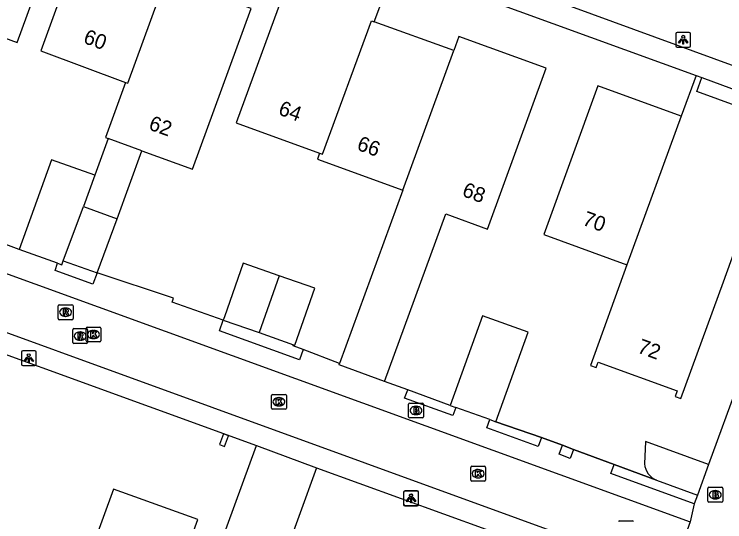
# Model space of a CAD drawing. Extents: x 155275 to 156263, y 382654 to 383635.
# Drawn here: x 156037.12 to 156084.89, y 383048.16 to 383082.31 of the extents above; entities that cross this region are included whole.
import ezdxf

# ---------------------------------------------------------------- set-up
doc = ezdxf.new("R2010")
doc.units = 0
for name, color, linetype in [('IMGEO_Brandkraan', 7, 'Continuous'), ('IMGEO_Haag', 7, 'Continuous'), ('IMGEO_Hek', 7, 'Continuous'), ('IMGEO_Kolk', 7, 'Continuous'), ('IMGEO_Lichtpunt', 7, 'Continuous'), ('IMGEO_Pand', 7, 'Continuous'), ('IMGEO_Pand_nummerreeks', 7, 'Continuous'), ('IMGEO_Rijbaan_lokaal_open', 7, 'Continuous'), ('IMGEO_Rioolput', 7, 'Continuous'), ('IMGEO_Voetpad_open', 7, 'Continuous')]:
    doc.layers.add(name, color=color, linetype=linetype)

msp = doc.modelspace()

# ---------------------------------------------------------------- linework, layer by layer
at = {"layer": 'IMGEO_Brandkraan'}
for p, q in [((156063.632, 383055.222), (156063.632, 383056.074)), ((156063.707, 383056.148), (156064.559, 383056.148)), ((156064.633, 383056.074), (156064.633, 383055.222)), ((156064.12, 383055.928), (156064.145, 383055.928)), ((156064.559, 383055.148), (156063.707, 383055.148)), ((156064.143, 383055.368), (156064.118, 383055.368)), ((156083.749, 383049.552), (156083.749, 383050.404)), ((156083.824, 383050.478), (156084.676, 383050.478)), ((156084.75, 383050.404), (156084.75, 383049.552)), ((156084.237, 383050.258), (156084.262, 383050.258)), ((156084.676, 383049.478), (156083.824, 383049.478)), ((156084.26, 383049.698), (156084.235, 383049.698))]:
    msp.add_line(p, q, dxfattribs=at)
for points in [[(156063.632, 383055.222), (156063.632, 383056.074)], [(156063.707, 383056.148), (156064.559, 383056.148)], [(156064.633, 383056.074), (156064.633, 383055.222)], [(156063.98, 383055.848), (156063.98, 383055.448), (156064.193, 383055.448)], [(156064.211, 383055.848), (156063.98, 383055.848)], [(156064.159, 383055.767), (156064.105, 383055.767), (156064.105, 383055.691)], [(156064.105, 383055.691), (156064.158, 383055.691)], [(156064.167, 383055.615), (156064.105, 383055.615), (156064.105, 383055.534)], [(156064.559, 383055.148), (156063.707, 383055.148)], [(156064.105, 383055.534), (156064.167, 383055.534)], [(156083.749, 383049.552), (156083.749, 383050.404)], [(156083.824, 383050.478), (156084.676, 383050.478)], [(156084.75, 383050.404), (156084.75, 383049.552)], [(156084.097, 383050.178), (156084.097, 383049.778), (156084.31, 383049.778)], [(156084.328, 383050.178), (156084.097, 383050.178)], [(156084.276, 383050.097), (156084.222, 383050.097), (156084.222, 383050.021)], [(156084.222, 383050.021), (156084.275, 383050.021)], [(156084.284, 383049.945), (156084.222, 383049.945), (156084.222, 383049.864)], [(156084.222, 383049.864), (156084.284, 383049.864)], [(156084.676, 383049.478), (156083.824, 383049.478)]]:
    msp.add_lwpolyline(points, dxfattribs=at)
for centre, radius, start, end in [((156063.709, 383056.072), 0.0765, 91.552, 178.448), ((156063.709, 383056.072), 0.0765, 91.552, 178.448), ((156064.557, 383056.072), 0.0765, 1.552, 88.448), ((156064.557, 383056.072), 0.0765, 1.552, 88.448), ((156064.16, 383055.729), 0.0379, 267.8285, 90.9355), ((156064.168, 383055.574), 0.0404, 269.8759, 90.5077), ((156064.215, 383055.703), 0.145, 59.4692, 91.5367), ((156064.24, 383055.75), 0.0922, 285.5137, 58.1501), ((156064.245, 383055.558), 0.105, 301.3115, 78.989), ((156063.709, 383055.224), 0.0765, 181.552, 268.448), ((156063.709, 383055.224), 0.0765, 181.552, 268.448), ((156064.199, 383055.699), 0.251, 268.6676, 293.5347), ((156064.557, 383055.224), 0.0765, 271.552, 358.448), ((156064.557, 383055.224), 0.0765, 271.552, 358.448), ((156083.826, 383050.402), 0.0765, 91.552, 178.448), ((156083.826, 383050.402), 0.0765, 91.552, 178.448), ((156084.674, 383050.402), 0.0765, 1.552, 88.448), ((156084.674, 383050.402), 0.0765, 1.552, 88.448), ((156084.277, 383050.059), 0.0379, 267.8285, 90.9355), ((156084.285, 383049.904), 0.0404, 269.8759, 90.5077), ((156084.332, 383050.033), 0.145, 59.4692, 91.5367), ((156084.357, 383050.08), 0.0922, 285.5137, 58.1501), ((156084.362, 383049.888), 0.105, 301.3115, 78.989), ((156083.826, 383049.554), 0.0765, 181.552, 268.448), ((156083.826, 383049.554), 0.0765, 181.552, 268.448), ((156084.316, 383050.029), 0.251, 268.6676, 293.5347), ((156084.674, 383049.554), 0.0765, 271.552, 358.448), ((156084.674, 383049.554), 0.0765, 271.552, 358.448)]:
    msp.add_arc(centre, radius, start, end, dxfattribs=at)
for centre, major_axis, ratio, start_param, end_param in [((156064.119, 383055.648), (-0.387, 0.002), 0.722429, 4.712389, 7.853982), ((156064.144, 383055.648), (-0.39, 0.002), 0.717154, 1.570796, 4.712389), ((156084.236, 383049.978), (-0.387, 0.002), 0.722429, 4.712389, 7.853982), ((156084.261, 383049.978), (-0.39, 0.002), 0.717154, 1.570796, 4.712389)]:
    msp.add_ellipse(centre, major_axis=major_axis, ratio=ratio, start_param=start_param, end_param=end_param, dxfattribs=at)
at = {"layer": 'IMGEO_Haag'}
for points in [[(156056.538, 383059.74), (156055.881, 383059.988), (156055.893, 383060.071)], [(156066.438, 383055.99), (156063.572, 383057.025)], [(156072.572, 383053.834), (156069.494, 383054.888)], [(156074.726, 383053.032), (156073.973, 383053.312)], [(156080.31, 383050.95), (156077.462, 383052.012)]]:
    msp.add_lwpolyline(points, dxfattribs=at)
at = {"layer": 'IMGEO_Hek'}
for points in [[(156047.832, 383063.194), (156042.707, 383064.903)], [(156056.538, 383059.74), (156055.881, 383059.988), (156055.893, 383060.071)], [(156059, 383058.81), (156056.538, 383059.74)], [(156069.494, 383054.888), (156072.572, 383053.834)], [(156072.572, 383053.834), (156073.973, 383053.312)], [(156073.973, 383053.312), (156074.726, 383053.032)], [(156074.726, 383053.032), (156077.462, 383052.012)], [(156057.443, 383051.791), (156068.83, 383047.669)], [(156077.462, 383052.012), (156080.31, 383050.95)]]:
    msp.add_lwpolyline(points, dxfattribs=at)
at = {"layer": 'IMGEO_Kolk'}
for p, q in [((156041.95, 383060.332), (156041.95, 383061.184)), ((156042.025, 383061.258), (156042.877, 383061.258)), ((156042.438, 383061.038), (156042.463, 383061.038)), ((156042.951, 383061.184), (156042.951, 383060.332)), ((156042.461, 383060.478), (156042.436, 383060.478)), ((156042.877, 383060.258), (156042.025, 383060.258)), ((156054.414, 383055.804), (156054.414, 383056.656)), ((156054.489, 383056.73), (156055.341, 383056.73)), ((156055.415, 383056.656), (156055.415, 383055.804)), ((156054.902, 383056.51), (156054.927, 383056.51)), ((156055.341, 383055.73), (156054.489, 383055.73)), ((156054.925, 383055.95), (156054.9, 383055.95)), ((156067.81, 383050.968), (156067.81, 383051.82)), ((156067.885, 383051.894), (156068.737, 383051.894)), ((156068.811, 383051.82), (156068.811, 383050.968)), ((156068.298, 383051.674), (156068.323, 383051.674)), ((156068.737, 383050.894), (156067.885, 383050.894)), ((156068.321, 383051.114), (156068.296, 383051.114)), ((156077.821, 383048.231), (156078.673, 383048.231))]:
    msp.add_line(p, q, dxfattribs=at)
for points in [[(156041.95, 383060.332), (156041.95, 383061.184)], [(156042.025, 383061.258), (156042.877, 383061.258)], [(156042.271, 383060.958), (156042.394, 383060.958), (156042.394, 383060.807), (156042.524, 383060.958), (156042.688, 383060.958), (156042.542, 383060.807), (156042.695, 383060.558), (156042.543, 383060.558), (156042.458, 383060.722), (156042.394, 383060.655), (156042.394, 383060.558), (156042.271, 383060.558), (156042.271, 383060.958)], [(156042.951, 383061.184), (156042.951, 383060.332)], [(156042.877, 383060.258), (156042.025, 383060.258)], [(156054.414, 383055.804), (156054.414, 383056.656)], [(156054.489, 383056.73), (156055.341, 383056.73)], [(156055.415, 383056.656), (156055.415, 383055.804)], [(156054.735, 383056.43), (156054.858, 383056.43), (156054.858, 383056.279), (156054.988, 383056.43), (156055.152, 383056.43), (156055.006, 383056.279), (156055.159, 383056.03), (156055.007, 383056.03), (156054.922, 383056.194), (156054.858, 383056.127), (156054.858, 383056.03), (156054.735, 383056.03), (156054.735, 383056.43)], [(156055.341, 383055.73), (156054.489, 383055.73)], [(156067.81, 383050.968), (156067.81, 383051.82)], [(156067.885, 383051.894), (156068.737, 383051.894)], [(156068.811, 383051.82), (156068.811, 383050.968)], [(156068.131, 383051.594), (156068.254, 383051.594), (156068.254, 383051.443), (156068.384, 383051.594), (156068.548, 383051.594), (156068.402, 383051.443), (156068.555, 383051.194), (156068.403, 383051.194), (156068.318, 383051.358), (156068.254, 383051.291), (156068.254, 383051.194), (156068.131, 383051.194), (156068.131, 383051.594)], [(156068.737, 383050.894), (156067.885, 383050.894)], [(156077.821, 383048.231), (156078.673, 383048.231)]]:
    msp.add_lwpolyline(points, dxfattribs=at)
for centre, start, end in [((156042.027, 383061.182), 91.552, 178.448), ((156042.027, 383061.182), 91.552, 178.448), ((156042.875, 383061.182), 1.552, 88.448), ((156042.875, 383061.182), 1.552, 88.448), ((156042.027, 383060.334), 181.552, 268.448), ((156042.027, 383060.334), 181.552, 268.448), ((156042.875, 383060.334), 271.552, 358.448), ((156042.875, 383060.334), 271.552, 358.448), ((156054.491, 383056.654), 91.552, 178.448), ((156054.491, 383056.654), 91.552, 178.448), ((156055.339, 383056.654), 1.552, 88.448), ((156055.339, 383056.654), 1.552, 88.448), ((156054.491, 383055.806), 181.552, 268.448), ((156054.491, 383055.806), 181.552, 268.448), ((156055.339, 383055.806), 271.552, 358.448), ((156055.339, 383055.806), 271.552, 358.448), ((156067.887, 383051.818), 91.552, 178.448), ((156067.887, 383051.818), 91.552, 178.448), ((156068.735, 383051.818), 1.552, 88.448), ((156068.735, 383051.818), 1.552, 88.448), ((156067.887, 383050.97), 181.552, 268.448), ((156067.887, 383050.97), 181.552, 268.448), ((156068.735, 383050.97), 271.552, 358.448), ((156068.735, 383050.97), 271.552, 358.448), ((156077.823, 383048.155), 91.552, 178.448), ((156077.823, 383048.155), 91.552, 178.448), ((156078.671, 383048.155), 1.552, 88.448), ((156078.671, 383048.155), 1.552, 88.448)]:
    msp.add_arc(centre, 0.0765, start, end, dxfattribs=at)
for centre, major_axis, ratio, start_param, end_param in [((156042.437, 383060.758), (-0.387, 0.002), 0.722429, 4.712389, 7.853982), ((156042.462, 383060.758), (-0.39, 0.002), 0.717154, 1.570796, 4.712389), ((156054.901, 383056.23), (-0.387, 0.002), 0.722429, 4.712389, 7.853982), ((156054.926, 383056.23), (-0.39, 0.002), 0.717154, 1.570796, 4.712389), ((156068.297, 383051.394), (-0.387, 0.002), 0.722429, 4.712389, 7.853982), ((156068.322, 383051.394), (-0.39, 0.002), 0.717154, 1.570796, 4.712389)]:
    msp.add_ellipse(centre, major_axis=major_axis, ratio=ratio, start_param=start_param, end_param=end_param, dxfattribs=at)
at = {"layer": 'IMGEO_Lichtpunt'}
for p, q in [((156081.597, 383080.992), (156081.597, 383080.185)), ((156081.597, 383080.992), (156081.597, 383080.185)), ((156082.499, 383081.087), (156081.691, 383081.087)), ((156082.499, 383081.087), (156081.691, 383081.087)), ((156082.593, 383080.185), (156082.593, 383080.992)), ((156082.593, 383080.185), (156082.593, 383080.992)), ((156081.691, 383080.091), (156082.499, 383080.091)), ((156081.691, 383080.091), (156082.499, 383080.091)), ((156037.602, 383059.563), (156037.602, 383058.756)), ((156037.602, 383059.563), (156037.602, 383058.756)), ((156038.504, 383059.658), (156037.696, 383059.658)), ((156038.504, 383059.658), (156037.696, 383059.658)), ((156038.598, 383058.756), (156038.598, 383059.563)), ((156038.598, 383058.756), (156038.598, 383059.563)), ((156037.696, 383058.662), (156038.504, 383058.662)), ((156037.696, 383058.662), (156038.504, 383058.662)), ((156063.298, 383050.129), (156063.298, 383049.322)), ((156063.298, 383050.129), (156063.298, 383049.322)), ((156063.299, 383050.149), (156063.299, 383049.342)), ((156063.299, 383050.149), (156063.299, 383049.342)), ((156064.2, 383050.224), (156063.392, 383050.224)), ((156064.2, 383050.224), (156063.392, 383050.224)), ((156064.201, 383050.244), (156063.393, 383050.244)), ((156064.201, 383050.244), (156063.393, 383050.244)), ((156064.294, 383049.322), (156064.294, 383050.129)), ((156064.294, 383049.322), (156064.294, 383050.129)), ((156064.295, 383049.342), (156064.295, 383050.149)), ((156064.295, 383049.342), (156064.295, 383050.149)), ((156063.392, 383049.228), (156064.2, 383049.228)), ((156063.392, 383049.228), (156064.2, 383049.228)), ((156063.393, 383049.248), (156064.201, 383049.248)), ((156063.393, 383049.248), (156064.201, 383049.248))]:
    msp.add_line(p, q, dxfattribs=at)
for points in [[(156081.971, 383080.656), (156082.01, 383080.628), (156081.822, 383080.366), (156081.784, 383080.393), (156081.971, 383080.656)], [(156082.073, 383080.608), (156082.12, 383080.608), (156082.12, 383080.286), (156082.073, 383080.286), (156082.073, 383080.608)], [(156082.183, 383080.628), (156082.221, 383080.655), (156082.408, 383080.393), (156082.369, 383080.365), (156082.183, 383080.628)], [(156037.976, 383059.227), (156038.015, 383059.199), (156037.827, 383058.937), (156037.789, 383058.964), (156037.976, 383059.227)], [(156038.078, 383059.179), (156038.125, 383059.179), (156038.125, 383058.857), (156038.078, 383058.857), (156038.078, 383059.179)], [(156038.188, 383059.199), (156038.226, 383059.226), (156038.413, 383058.964), (156038.374, 383058.936), (156038.188, 383059.199)], [(156063.672, 383049.793), (156063.711, 383049.765), (156063.523, 383049.503), (156063.485, 383049.53), (156063.672, 383049.793)], [(156063.673, 383049.813), (156063.712, 383049.785), (156063.524, 383049.523), (156063.486, 383049.55), (156063.673, 383049.813)], [(156063.774, 383049.745), (156063.821, 383049.745), (156063.821, 383049.423), (156063.774, 383049.423), (156063.774, 383049.745)], [(156063.775, 383049.765), (156063.822, 383049.765), (156063.822, 383049.443), (156063.775, 383049.443), (156063.775, 383049.765)], [(156063.884, 383049.765), (156063.922, 383049.792), (156064.109, 383049.53), (156064.07, 383049.502), (156063.884, 383049.765)], [(156063.885, 383049.785), (156063.923, 383049.812), (156064.11, 383049.55), (156064.071, 383049.522), (156063.885, 383049.785)]]:
    msp.add_lwpolyline(points, dxfattribs=at)
for centre in [(156082.096, 383080.79), (156038.101, 383059.361), (156063.797, 383049.927), (156063.798, 383049.947)]:
    msp.add_circle(centre, 0.0994, dxfattribs=at)
for centre, start, end in [((156081.691, 383080.992), 90, 180), ((156081.691, 383080.992), 90, 180), ((156082.499, 383080.992), 0, 90), ((156082.499, 383080.992), 0, 90), ((156081.691, 383080.185), 180, 270), ((156081.691, 383080.185), 180, 270), ((156082.499, 383080.185), 270, 0), ((156082.499, 383080.185), 270, 360), ((156037.696, 383059.563), 90, 180), ((156037.696, 383059.563), 90, 180), ((156038.504, 383059.563), 0, 90), ((156038.504, 383059.563), 0, 90), ((156037.696, 383058.756), 180, 270), ((156037.696, 383058.756), 180, 270), ((156038.504, 383058.756), 270, 0), ((156038.504, 383058.756), 270, 360), ((156063.392, 383050.129), 90, 180), ((156063.392, 383050.129), 90, 180), ((156063.393, 383050.149), 90, 180), ((156063.393, 383050.149), 90, 180), ((156064.2, 383050.129), 0, 90), ((156064.2, 383050.129), 0, 90), ((156064.201, 383050.149), 0, 90), ((156064.201, 383050.149), 0, 90), ((156063.392, 383049.322), 180, 270), ((156063.392, 383049.322), 180, 270), ((156063.393, 383049.342), 180, 270), ((156063.393, 383049.342), 180, 270), ((156064.2, 383049.322), 270, 0), ((156064.2, 383049.322), 270, 360), ((156064.201, 383049.342), 270, 0), ((156064.201, 383049.342), 270, 360)]:
    msp.add_arc(centre, 0.0946, start, end, dxfattribs=at)
at = {"layer": 'IMGEO_Pand'}
for points in [[(156040.934, 383090.292), (156035.052, 383092.422), (156031.469, 383082.549), (156037.327, 383080.406), (156040.934, 383090.292)], [(156047.487, 383084.709), (156048.533, 383087.587), (156042.528, 383089.794), (156038.908, 383079.832), (156044.599, 383077.722)], [(156044.599, 383077.722), (156044.753, 383077.666), (156047.336, 383084.763), (156047.487, 383084.709)], [(156061.326, 383081.795), (156061.697, 383082.809), (156055.694, 383085.005), (156052.031, 383074.995), (156057.654, 383072.95)], [(156045.703, 383073.119), (156049.109, 383071.888), (156053.054, 383082.682), (156047.487, 383084.709)], [(156057.654, 383072.95), (156057.847, 383072.88), (156061.133, 383081.865), (156061.326, 383081.795)], [(156066.672, 383079.859), (156061.326, 383081.795)], [(156062.01, 383057.589), (156066.131, 383068.883), (156068.934, 383067.848), (156072.883, 383078.667), (156067.013, 383080.799), (156066.672, 383079.859)], [(156063.238, 383070.466), (156066.672, 383079.859)], [(156082.964, 383078.192), (156081.966, 383075.45)], [(156082.964, 383078.192), (156083.338, 383078.054)], [(156089.149, 383075.906), (156088.653, 383075.038), (156083.004, 383077.115), (156083.338, 383078.054)], [(156044.599, 383077.722), (156043.247, 383074.007), (156043.442, 383073.937)], [(156081.966, 383075.45), (156076.348, 383077.489), (156072.716, 383067.482), (156078.317, 383065.442)], [(156078.317, 383065.442), (156075.871, 383058.662), (156076.255, 383058.527), (156076.388, 383058.904), (156081.692, 383056.957), (156081.554, 383056.581), (156081.929, 383056.444), (156084.796, 383064.304), (156085.874, 383067.285), (156087.897, 383072.844), (156089.519, 383075.751)], [(156081.966, 383075.45), (156078.317, 383065.442)], [(156043.442, 383073.937), (156042.534, 383071.471)], [(156045.703, 383073.119), (156043.442, 383073.937)], [(156044.037, 383068.551), (156045.703, 383073.119)], [(156057.654, 383072.95), (156057.508, 383072.555), (156063.238, 383070.466)], [(156042.534, 383071.471), (156039.636, 383072.501), (156037.447, 383066.478)], [(156042.534, 383071.471), (156041.772, 383069.375)], [(156063.238, 383070.466), (156059, 383058.81)], [(156040.418, 383065.724), (156041.772, 383069.375)], [(156041.772, 383069.375), (156044.037, 383068.551)], [(156042.707, 383064.903), (156044.037, 383068.551)], [(156040.04, 383065.551), (156037.447, 383066.478)], [(156040.04, 383065.551), (156040.321, 383065.451), (156040.418, 383065.724)], [(156040.418, 383065.724), (156042.707, 383064.903)], [(156054.926, 383064.711), (156052.521, 383065.556), (156051.254, 383061.952), (156051.176, 383061.73)], [(156054.926, 383064.711), (156053.58, 383060.884)], [(156055.893, 383060.071), (156055.995, 383060.034), (156057.33, 383063.865), (156054.926, 383064.711)], [(156069.494, 383054.888), (156071.666, 383060.912), (156068.61, 383062.014), (156066.438, 383055.99)], [(156051.176, 383061.73), (156053.58, 383060.884)], [(156053.58, 383060.884), (156055.893, 383060.071)], [(156062.01, 383057.589), (156058.969, 383058.727), (156059, 383058.81)], [(156066.438, 383055.99), (156066.81, 383055.856)], [(156069.094, 383055.033), (156066.81, 383055.856)], [(156069.094, 383055.033), (156069.494, 383054.888)], [(156051.26, 383053.225), (156051.525, 383053.951), (156051.183, 383054.076), (156050.918, 383053.35), (156051.26, 383053.225)], [(156057.443, 383051.791), (156055.072, 383045.24), (156051.008, 383046.712), (156053.405, 383053.282)], [(156053.405, 383053.282), (156057.443, 383051.791)], [(156083.798, 383052.015), (156079.57, 383053.553), (156079.494, 383052.064)], [(156083.798, 383052.015), (156083.05, 383049.96)], [(156080.31, 383050.95), (156083.05, 383049.96)], [(156034.938, 383038.163), (156033.253, 383033.543), (156040.862, 383030.722), (156040.756, 383030.424), (156041.071, 383030.305), (156041.182, 383030.603), (156041.974, 383032.711), (156043.574, 383032.131), (156049.467, 383048.305), (156043.787, 383050.353), (156040.679, 383041.803), (156038.838, 383036.74), (156034.938, 383038.163)]]:
    msp.add_lwpolyline(points, dxfattribs=at)
msp.add_arc((156080.832, 383052.188), 1.343, 185.2945, 247.1507, dxfattribs=at)
at = {"layer": 'IMGEO_Rijbaan_lokaal_open'}
for points in [[(156000.039, 383078.152), (156026.745, 383068.497), (156033.987, 383065.798), (156082.569, 383048.16)], [(156081.283, 383044.621), (155998.741, 383074.665)], [(156082.569, 383048.16), (156081.283, 383044.621)]]:
    msp.add_lwpolyline(points, dxfattribs=at)
at = {"layer": 'IMGEO_Rioolput'}
for p, q in [((156040.147, 383062.755), (156040.999, 383062.755)), ((156040.072, 383061.829), (156040.072, 383062.681)), ((156040.56, 383062.535), (156040.585, 383062.535)), ((156041.073, 383062.681), (156041.073, 383061.829)), ((156040.583, 383061.975), (156040.558, 383061.975)), ((156040.999, 383061.755), (156040.147, 383061.755)), ((156041.057, 383060.225), (156041.057, 383061.077)), ((156041.132, 383061.151), (156041.984, 383061.151)), ((156041.545, 383060.931), (156041.57, 383060.931)), ((156042.058, 383061.077), (156042.058, 383060.225)), ((156041.568, 383060.371), (156041.543, 383060.371)), ((156041.984, 383060.151), (156041.132, 383060.151))]:
    msp.add_line(p, q, dxfattribs=at)
for points in [[(156040.147, 383062.755), (156040.999, 383062.755)], [(156040.072, 383061.829), (156040.072, 383062.681)], [(156040.661, 383062.453), (156040.409, 383062.455), (156040.409, 383062.055)], [(156040.587, 383062.374), (156040.533, 383062.374), (156040.533, 383062.293)], [(156040.533, 383062.293), (156040.585, 383062.293)], [(156041.073, 383062.681), (156041.073, 383061.829)], [(156040.409, 383062.055), (156040.533, 383062.055), (156040.533, 383062.217), (156040.544, 383062.217)], [(156040.591, 383062.188), (156040.662, 383062.055), (156040.802, 383062.055), (156040.737, 383062.181)], [(156040.999, 383061.755), (156040.147, 383061.755)], [(156041.057, 383060.225), (156041.057, 383061.077)], [(156041.132, 383061.151), (156041.984, 383061.151)], [(156041.646, 383060.849), (156041.394, 383060.851), (156041.394, 383060.451)], [(156042.058, 383061.077), (156042.058, 383060.225)], [(156041.394, 383060.451), (156041.518, 383060.451), (156041.518, 383060.613), (156041.529, 383060.613)], [(156041.572, 383060.77), (156041.518, 383060.77), (156041.518, 383060.689)], [(156041.518, 383060.689), (156041.57, 383060.689)], [(156041.576, 383060.584), (156041.647, 383060.451), (156041.787, 383060.451), (156041.722, 383060.577)], [(156041.984, 383060.151), (156041.132, 383060.151)]]:
    msp.add_lwpolyline(points, dxfattribs=at)
for centre, radius, start, end in [((156040.149, 383062.679), 0.0765, 91.552, 178.448), ((156040.149, 383062.679), 0.0765, 91.552, 178.448), ((156040.997, 383062.679), 0.0765, 1.552, 88.448), ((156040.997, 383062.679), 0.0765, 1.552, 88.448), ((156040.569, 383062.482), 0.19, 274.7715, 282.9687), ((156040.593, 383062.278), 0.0964, 77.0061, 93.1865), ((156040.607, 383062.335), 0.0378, 276.6634, 79.6772), ((156040.66, 383062.343), 0.109, 350.3612, 89.416), ((156040.658, 383062.343), 0.112, 277.5842, 350.9817), ((156040.149, 383061.831), 0.0765, 181.552, 268.448), ((156040.149, 383061.831), 0.0765, 181.552, 268.448), ((156040.543, 383062.164), 0.0533, 26.0293, 88.6989), ((156040.642, 383062.128), 0.108, 29.5134, 73.7905), ((156040.997, 383061.831), 0.0765, 271.552, 358.448), ((156040.997, 383061.831), 0.0765, 271.552, 358.448), ((156041.134, 383061.075), 0.0765, 91.552, 178.448), ((156041.134, 383061.075), 0.0765, 91.552, 178.448), ((156041.645, 383060.739), 0.109, 350.3612, 89.416), ((156041.982, 383061.075), 0.0765, 1.552, 88.448), ((156041.982, 383061.075), 0.0765, 1.552, 88.448), ((156041.528, 383060.56), 0.0533, 26.0293, 88.6989), ((156041.554, 383060.878), 0.19, 274.7715, 282.9687), ((156041.578, 383060.674), 0.0964, 77.0061, 93.1865), ((156041.592, 383060.731), 0.0378, 276.6634, 79.6772), ((156041.643, 383060.739), 0.112, 277.5842, 350.9817), ((156041.627, 383060.524), 0.108, 29.5134, 73.7905), ((156041.134, 383060.227), 0.0765, 181.552, 268.448), ((156041.134, 383060.227), 0.0765, 181.552, 268.448), ((156041.982, 383060.227), 0.0765, 271.552, 358.448), ((156041.982, 383060.227), 0.0765, 271.552, 358.448)]:
    msp.add_arc(centre, radius, start, end, dxfattribs=at)
for centre, major_axis, ratio, start_param, end_param in [((156040.559, 383062.255), (-0.387, 0.002), 0.722429, 4.712389, 7.853982), ((156040.584, 383062.255), (-0.39, 0.002), 0.717154, 1.570796, 4.712389), ((156041.544, 383060.651), (-0.387, 0.002), 0.722429, 4.712389, 7.853982), ((156041.569, 383060.651), (-0.39, 0.002), 0.717154, 1.570796, 4.712389)]:
    msp.add_ellipse(centre, major_axis=major_axis, ratio=ratio, start_param=start_param, end_param=end_param, dxfattribs=at)
at = {"layer": 'IMGEO_Voetpad_open'}
for points in [[(156035.007, 383095.604), (156082.964, 383078.192)], [(156092.645, 383076.216), (156071.718, 383083.882), (156075.212, 383093.218), (156096.115, 383085.675)], [(156083.338, 383078.054), (156089.149, 383075.906)], [(156092.134, 383074.803), (156083.798, 383052.015)], [(156008.38, 383069.647), (156019.569, 383065.592), (156024.267, 383063.882), (156053.405, 383053.282)], [(156037.447, 383066.478), (156034.62, 383067.526), (156030.094, 383069.343)], [(156042.707, 383064.903), (156042.397, 383064.134), (156039.868, 383065.06), (156040.04, 383065.551)], [(156051.176, 383061.73), (156047.742, 383062.937), (156047.832, 383063.194), (156042.707, 383064.903)], [(156056.538, 383059.74), (156056.292, 383059.058), (156050.911, 383060.995), (156051.176, 383061.73)], [(156059, 383058.81), (156056.538, 383059.74)], [(156063.572, 383057.025), (156062.01, 383057.589)], [(156066.81, 383055.856), (156066.613, 383055.305), (156063.365, 383056.474), (156063.572, 383057.025)], [(156072.572, 383053.834), (156072.348, 383053.219), (156068.89, 383054.483), (156069.094, 383055.033)], [(156073.973, 383053.312), (156072.572, 383053.834)], [(156074.726, 383053.032), (156074.489, 383052.418), (156073.753, 383052.704), (156073.973, 383053.312)], [(156077.462, 383052.012), (156074.726, 383053.032)], [(156057.443, 383051.791), (156068.83, 383047.669)], [(156082.836, 383049.372), (156077.229, 383051.417), (156077.462, 383052.012)], [(156083.05, 383049.96), (156082.836, 383049.372)], [(156082.836, 383049.372), (156082.569, 383048.16)]]:
    msp.add_lwpolyline(points, dxfattribs=at)

# ---------------------------------------------------------------- texts
at = {"layer": 'IMGEO_Pand_nummerreeks'}
for s, rotation, p in [('60', 339.6572, (156041.706, 383080.394)), ('64', 340.0144, (156054.815, 383075.579)), ('62', 340.1241, (156046.097, 383074.572)), ('66', 339.9695, (156060.096, 383073.208)), ('68', 339.7335, (156067.171, 383070.098)), ('70', 339.9873, (156075.261, 383068.152)), ('72', 339.8433, (156078.951, 383059.561))]:
    msp.add_text(s, height=1, rotation=rotation, dxfattribs=at).set_placement(p)

doc.saveas('drawing.dxf')
